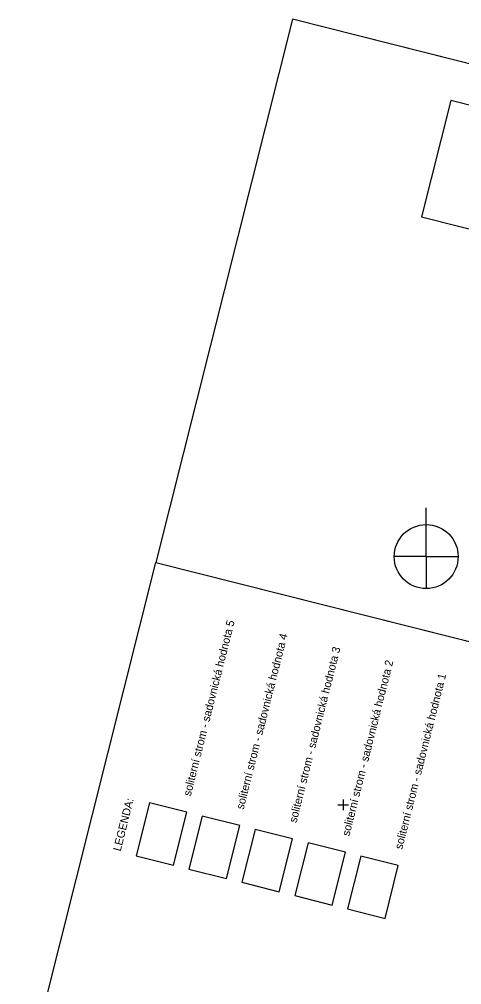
# Model space of a CAD drawing. Extents: x -740053 to -737517, y -1033516 to -1032488.
# Drawn here: x -739060.8 to -738977.7, y -1033083.7 to -1032902.7 of the extents above; entities that cross this region are included whole.
import ezdxf

# ---------------------------------------------------------------- set-up
doc = ezdxf.new("R2010")
doc.units = 0
for name, color, linetype in [('ctv-sit', 7, 'Continuous'), ('Predmety bez rozlišeni', 7, 'Continuous'), ('promika-formát', 7, 'Continuous'), ('promika-rozp-poznamky', 7, 'Continuous')]:
    doc.layers.add(name, color=color, linetype=linetype)

# ---------------------------------------------------------------- blocks, each defined once
blk = doc.blocks.new('ctvsit')
for p, q in [((2, 0), (-2, 0)), ((0, -2), (0, 2))]:
    blk.add_line(p, q)

msp = doc.modelspace()

# ---------------------------------------------------------------- linework, layer by layer
at = {"layer": 'Predmety bez rozlišeni'}
for p, q in [((-739009.5, -1032902.74), (-739035.13, -1033004.56)), ((-738865.49, -1032938.99), (-739009.5, -1032902.74)), ((-738984.39, -1033003.46), (-738984.39, -1032994.3)), ((-738984.39, -1033003.46), (-738990.39, -1033003.46)), ((-738984.39, -1033003.46), (-738978.39, -1033003.46)), ((-738984.39, -1033003.46), (-738984.39, -1033009.46)), ((-739060.76, -1033106.39), (-739035.13, -1033004.56)), ((-739035.13, -1033004.56), (-738891.12, -1033040.82))]:
    msp.add_line(p, q, dxfattribs=at)
for points in [[(-739031.82, -1033061.29), (-739029.32, -1033051.37), (-739036.33, -1033049.6), (-739038.83, -1033059.53)], [(-739021.89, -1033063.79), (-739019.39, -1033053.87), (-739026.41, -1033052.1), (-739028.91, -1033062.03)], [(-739011.97, -1033066.29), (-739009.47, -1033056.36), (-739016.48, -1033054.6), (-739018.98, -1033064.52)], [(-739002.04, -1033068.79), (-738999.54, -1033058.86), (-739006.56, -1033057.1), (-739009.06, -1033067.02)], [(-738992.12, -1033071.29), (-738989.62, -1033061.36), (-738996.64, -1033059.6), (-738999.13, -1033069.52)]]:
    msp.add_lwpolyline(points, close=True, dxfattribs=at)
msp.add_circle((-738984.39, -1033003.46), 6, dxfattribs=at)
at = {"layer": 'promika-formát'}
msp.add_lwpolyline([(-738891.12, -1033040.82), (-738865.49, -1032938.99), (-739009.5, -1032902.74), (-739035.13, -1033004.56)], close=True, dxfattribs=at)
at = {"layer": 'promika-rozp-poznamky'}
msp.add_lwpolyline([(-738963.46, -1032945.27), (-738957.96, -1032923.45), (-738979.78, -1032917.95), (-738985.27, -1032939.77)], close=True, dxfattribs=at)

# ---------------------------------------------------------------- block references
at = {"layer": 'ctv-sit', "xscale": 0.5, "yscale": 0.5, "rotation": 180}
msp.add_blockref('ctvsit', (-739000, -1033050), dxfattribs=at)

# ---------------------------------------------------------------- texts
at = {"layer": 'Predmety bez rozlišeni'}
for s, p in [('soliterní strom - sadovnická hodnota 5', (-739028.59, -1033048.46)), ('soliterní strom - sadovnická hodnota 4', (-739018.66, -1033050.96)), ('soliterní strom - sadovnická hodnota 3', (-739008.74, -1033053.46)), ('soliterní strom - sadovnická hodnota 2 ', (-738998.81, -1033055.95)), ('soliterní strom - sadovnická hodnota 1', (-738988.89, -1033058.45)), ('LEGENDA:', (-739041.74, -1033058.79))]:
    msp.add_text(s, height=1.5, rotation=75.8698, dxfattribs=at).set_placement(p)

doc.saveas('drawing.dxf')
